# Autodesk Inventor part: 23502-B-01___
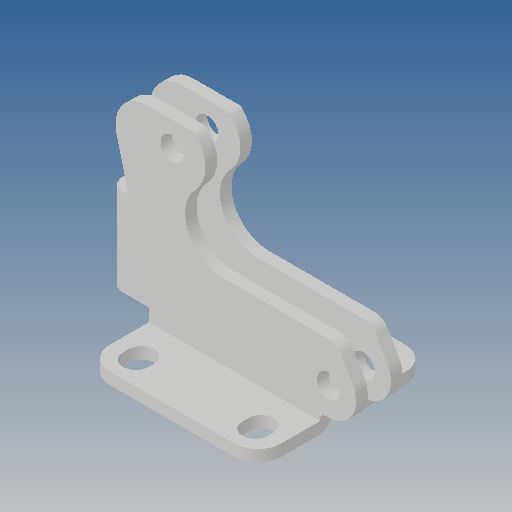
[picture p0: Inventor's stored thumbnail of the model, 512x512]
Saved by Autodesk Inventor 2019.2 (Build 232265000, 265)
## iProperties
Created: 2010-06
Part Number: 23502-B-01___
Material: Ogólny
Document SubType Name: Modeling
Designer: CADENGINEERING4
Density: 1 g/cm^3
Appearance: Domyślna
Author: CADENGINEERING4
Revision Number: ANY
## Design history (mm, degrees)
feature "NONE"
node "Bryła1"
